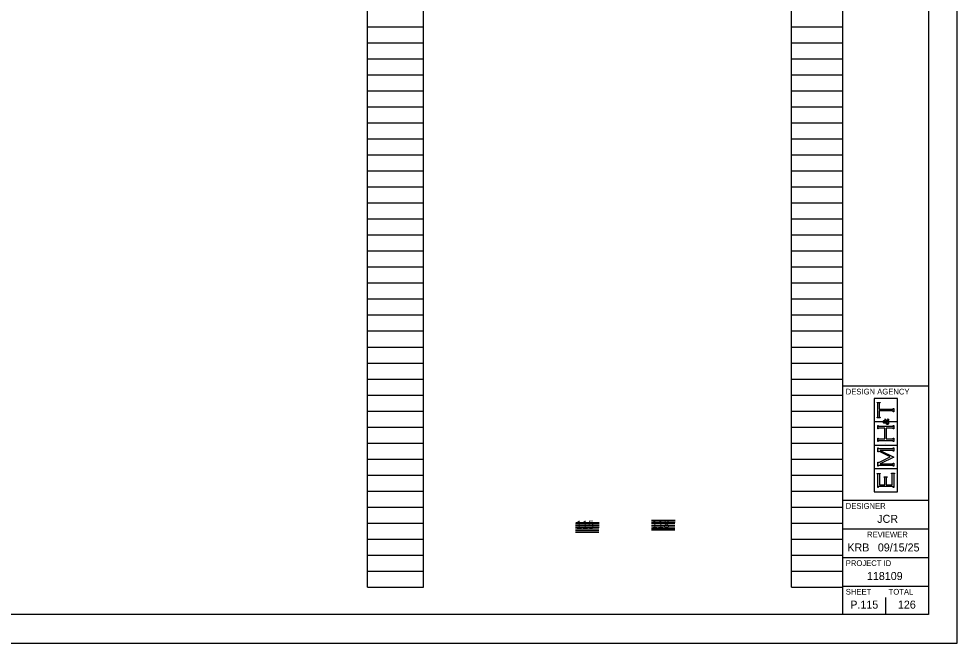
# Model space of a CAD drawing. Extents: x 0 to 34, y 0 to 22.
# Drawn here: x 17.58 to 34, y 0 to 10.92 of the extents above; entities that cross this region are included whole.
import ezdxf

# ---------------------------------------------------------------- set-up
doc = ezdxf.new("R2010")
doc.units = 0
for name, color, linetype in [('SH_Border', 7, 'Continuous'), ('SH_Cut_Line', 7, 'Continuous'), ('SH_Data', 7, 'Continuous'), ('SH_Text', 7, 'Continuous')]:
    doc.layers.add(name, color=color, linetype=linetype)

msp = doc.modelspace()

# ---------------------------------------------------------------- linework, layer by layer
at = {"layer": 'SH_Border'}
for p, q in [((32, 0.5), (32, 21.5)), ((32, 4.5), (33.5, 4.5)), ((32, 2.5), (33.5, 2.5)), ((32, 2), (33.5, 2)), ((32, 1.5), (33.5, 1.5)), ((32, 1), (33.5, 1))]:
    msp.add_line(p, q, dxfattribs=at)
msp.add_lwpolyline([(1.5, 21.5), (33.5, 21.5), (33.5, 0.5), (1.5, 0.5)], close=True, dxfattribs=at)
at = {"layer": 'SH_Cut_Line'}
msp.add_lwpolyline([(0, 0), (34, 0), (34, 22), (0, 22)], close=True, dxfattribs=at)
at = {"layer": 'SH_Data'}
for p, q in [((23.68, 0.98), (23.68, 21.14)), ((24.66, 0.98), (24.66, 21.14)), ((31.1, 0.98), (31.1, 21.14)), ((32, 0.98), (32, 21.14)), ((23.68, 10.78), (24.66, 10.78)), ((31.1, 10.78), (32, 10.78)), ((23.68, 10.5), (24.66, 10.5)), ((31.1, 10.5), (32, 10.5)), ((23.68, 10.22), (24.66, 10.22)), ((31.1, 10.22), (32, 10.22)), ((23.68, 9.94), (24.66, 9.94)), ((31.1, 9.94), (32, 9.94)), ((23.68, 9.66), (24.66, 9.66)), ((31.1, 9.66), (32, 9.66)), ((23.68, 9.38), (24.66, 9.38)), ((31.1, 9.38), (32, 9.38)), ((23.68, 9.1), (24.66, 9.1)), ((31.1, 9.1), (32, 9.1)), ((23.68, 8.82), (24.66, 8.82)), ((31.1, 8.82), (32, 8.82)), ((23.68, 8.54), (24.66, 8.54)), ((31.1, 8.54), (32, 8.54)), ((23.68, 8.26), (24.66, 8.26)), ((31.1, 8.26), (32, 8.26)), ((23.68, 7.98), (24.66, 7.98)), ((31.1, 7.98), (32, 7.98)), ((23.68, 7.7), (24.66, 7.7)), ((31.1, 7.7), (32, 7.7)), ((23.68, 7.42), (24.66, 7.42)), ((31.1, 7.42), (32, 7.42)), ((23.68, 7.14), (24.66, 7.14)), ((31.1, 7.14), (32, 7.14)), ((23.68, 6.86), (24.66, 6.86)), ((31.1, 6.86), (32, 6.86)), ((23.68, 6.58), (24.66, 6.58)), ((31.1, 6.58), (32, 6.58)), ((23.68, 6.3), (24.66, 6.3)), ((31.1, 6.3), (32, 6.3)), ((23.68, 6.02), (24.66, 6.02)), ((31.1, 6.02), (32, 6.02)), ((23.68, 5.74), (24.66, 5.74)), ((31.1, 5.74), (32, 5.74)), ((23.68, 5.46), (24.66, 5.46)), ((31.1, 5.46), (32, 5.46)), ((23.68, 5.18), (24.66, 5.18)), ((31.1, 5.18), (32, 5.18)), ((23.68, 4.9), (24.66, 4.9)), ((31.1, 4.9), (32, 4.9)), ((23.68, 4.62), (24.66, 4.62)), ((31.1, 4.62), (32, 4.62)), ((23.68, 4.34), (24.66, 4.34)), ((31.1, 4.34), (32, 4.34)), ((32.952, 4.279), (32.547, 4.279)), ((32.547, 4.279), (32.547, 3.875)), ((32.952, 3.875), (32.952, 4.279)), ((32.598, 4.204), (32.598, 4.211)), ((32.598, 4.211), (32.65, 4.211)), ((32.603, 4.203), (32.598, 4.204)), ((32.606, 4.201), (32.603, 4.203)), ((32.608, 4.199), (32.606, 4.201)), ((32.61, 4.196), (32.608, 4.199)), ((32.611, 4.192), (32.61, 4.196)), ((32.611, 4.187), (32.611, 4.192)), ((32.611, 3.968), (32.611, 4.187)), ((32.638, 4.196), (32.637, 4.192)), ((32.637, 4.192), (32.637, 4.187)), ((32.637, 4.187), (32.637, 4.093)), ((32.64, 4.199), (32.638, 4.196)), ((32.642, 4.201), (32.64, 4.199)), ((32.645, 4.203), (32.642, 4.201)), ((32.65, 4.204), (32.645, 4.203)), ((32.65, 4.211), (32.65, 4.204)), ((32.88, 4.101), (32.881, 4.106)), ((32.881, 4.106), (32.888, 4.106)), ((32.888, 4.106), (32.888, 4.048)), ((23.68, 4.06), (24.66, 4.06)), ((31.1, 4.06), (32, 4.06)), ((32.598, 3.95), (32.603, 3.951)), ((32.598, 3.944), (32.598, 3.95)), ((32.65, 3.944), (32.598, 3.944)), ((32.603, 3.951), (32.606, 3.953)), ((32.606, 3.953), (32.608, 3.955)), ((32.608, 3.955), (32.61, 3.958)), ((32.61, 3.958), (32.611, 3.962)), ((32.611, 3.962), (32.611, 3.968)), ((32.637, 4.093), (32.864, 4.093)), ((32.864, 4.061), (32.637, 4.061)), ((32.637, 4.061), (32.637, 3.968)), ((32.637, 3.968), (32.637, 3.962)), ((32.637, 3.962), (32.638, 3.958)), ((32.638, 3.958), (32.64, 3.955)), ((32.64, 3.955), (32.642, 3.953)), ((32.642, 3.953), (32.645, 3.951)), ((32.645, 3.951), (32.65, 3.95)), ((32.65, 3.95), (32.65, 3.944)), ((32.864, 4.093), (32.869, 4.093)), ((32.87, 4.061), (32.864, 4.061)), ((32.869, 4.093), (32.873, 4.094)), ((32.874, 4.06), (32.87, 4.061)), ((32.873, 4.094), (32.876, 4.096)), ((32.876, 4.059), (32.874, 4.06)), ((32.876, 4.096), (32.878, 4.097)), ((32.878, 4.057), (32.876, 4.059)), ((32.878, 4.097), (32.88, 4.101)), ((32.88, 4.053), (32.878, 4.057)), ((32.881, 4.048), (32.88, 4.053)), ((32.888, 4.048), (32.881, 4.048)), ((23.68, 3.78), (24.66, 3.78)), ((31.1, 3.78), (32, 3.78)), ((32.547, 3.875), (32.696, 3.875)), ((32.696, 3.869), (32.547, 3.869)), ((32.547, 3.869), (32.547, 3.465)), ((32.611, 3.749), (32.611, 3.807)), ((32.611, 3.807), (32.617, 3.807)), ((32.617, 3.807), (32.619, 3.802)), ((32.619, 3.802), (32.62, 3.798)), ((32.62, 3.798), (32.623, 3.797)), ((32.623, 3.797), (32.625, 3.795)), ((32.625, 3.795), (32.629, 3.794)), ((32.629, 3.794), (32.635, 3.794)), ((32.635, 3.794), (32.864, 3.794)), ((32.696, 3.875), (32.696, 3.869)), ((32.703, 3.879), (32.705, 3.883)), ((32.703, 3.873), (32.703, 3.879)), ((32.703, 3.868), (32.703, 3.873)), ((32.705, 3.863), (32.703, 3.868)), ((32.705, 3.883), (32.708, 3.887)), ((32.708, 3.858), (32.705, 3.863)), ((32.708, 3.887), (32.711, 3.89)), ((32.709, 3.879), (32.708, 3.876)), ((32.708, 3.876), (32.708, 3.873)), ((32.708, 3.873), (32.708, 3.869)), ((32.708, 3.869), (32.71, 3.866)), ((32.712, 3.853), (32.708, 3.858)), ((32.712, 3.881), (32.709, 3.879)), ((32.71, 3.866), (32.712, 3.864)), ((32.711, 3.89), (32.715, 3.892)), ((32.714, 3.883), (32.712, 3.881)), ((32.712, 3.864), (32.715, 3.862)), ((32.718, 3.85), (32.712, 3.853)), ((32.716, 3.884), (32.714, 3.883)), ((32.715, 3.892), (32.72, 3.892)), ((32.715, 3.862), (32.718, 3.861)), ((32.72, 3.884), (32.716, 3.884)), ((32.718, 3.861), (32.721, 3.861)), ((32.726, 3.85), (32.718, 3.85)), ((32.72, 3.892), (32.725, 3.892)), ((32.724, 3.884), (32.72, 3.884)), ((32.721, 3.861), (32.723, 3.861)), ((32.723, 3.861), (32.725, 3.862)), ((32.728, 3.882), (32.724, 3.884)), ((32.725, 3.892), (32.729, 3.89)), ((32.725, 3.862), (32.728, 3.862)), ((32.729, 3.85), (32.726, 3.85)), ((32.731, 3.88), (32.728, 3.882)), ((32.728, 3.862), (32.731, 3.863)), ((32.729, 3.89), (32.732, 3.887)), ((32.731, 3.85), (32.729, 3.85)), ((32.734, 3.877), (32.731, 3.88)), ((32.731, 3.863), (32.735, 3.865)), ((32.734, 3.851), (32.731, 3.85)), ((32.732, 3.887), (32.736, 3.883)), ((32.737, 3.872), (32.734, 3.877)), ((32.737, 3.852), (32.734, 3.851)), ((32.735, 3.865), (32.74, 3.867)), ((32.736, 3.883), (32.74, 3.878)), ((32.74, 3.867), (32.737, 3.872)), ((32.741, 3.853), (32.737, 3.852)), ((32.738, 3.893), (32.738, 3.922)), ((32.738, 3.922), (32.741, 3.922)), ((32.741, 3.893), (32.738, 3.893)), ((32.74, 3.878), (32.744, 3.869)), ((32.741, 3.922), (32.741, 3.918)), ((32.741, 3.918), (32.742, 3.915)), ((32.742, 3.896), (32.741, 3.895)), ((32.741, 3.895), (32.741, 3.893)), ((32.746, 3.855), (32.741, 3.853)), ((32.742, 3.915), (32.743, 3.913)), ((32.743, 3.897), (32.742, 3.896)), ((32.743, 3.913), (32.745, 3.911)), ((32.745, 3.899), (32.743, 3.897)), ((32.744, 3.869), (32.754, 3.875)), ((32.745, 3.911), (32.749, 3.908)), ((32.746, 3.899), (32.745, 3.899)), ((32.748, 3.899), (32.746, 3.899)), ((32.752, 3.844), (32.746, 3.855)), ((32.755, 3.899), (32.748, 3.899)), ((32.749, 3.908), (32.756, 3.904)), ((32.756, 3.86), (32.751, 3.857)), ((32.751, 3.857), (32.754, 3.852)), ((32.757, 3.837), (32.752, 3.844)), ((32.754, 3.875), (32.764, 3.881)), ((32.754, 3.852), (32.757, 3.848)), ((32.763, 3.895), (32.755, 3.899)), ((32.756, 3.904), (32.763, 3.9)), ((32.761, 3.863), (32.756, 3.86)), ((32.757, 3.848), (32.761, 3.845)), ((32.763, 3.833), (32.757, 3.837)), ((32.764, 3.865), (32.761, 3.863)), ((32.761, 3.845), (32.765, 3.843)), ((32.763, 3.9), (32.77, 3.896)), ((32.772, 3.887), (32.763, 3.895)), ((32.768, 3.829), (32.763, 3.833)), ((32.764, 3.881), (32.772, 3.887)), ((32.768, 3.867), (32.764, 3.865)), ((32.765, 3.843), (32.769, 3.841)), ((32.774, 3.872), (32.768, 3.867)), ((32.774, 3.827), (32.768, 3.829)), ((32.769, 3.841), (32.773, 3.841)), ((32.77, 3.896), (32.776, 3.891)), ((32.773, 3.841), (32.778, 3.841)), ((32.782, 3.878), (32.774, 3.872)), ((32.779, 3.827), (32.774, 3.827)), ((32.776, 3.891), (32.781, 3.895)), ((32.778, 3.841), (32.782, 3.843)), ((32.779, 3.923), (32.781, 3.926)), ((32.782, 3.922), (32.779, 3.923)), ((32.785, 3.827), (32.779, 3.827)), ((32.781, 3.926), (32.787, 3.924)), ((32.781, 3.895), (32.784, 3.898)), ((32.785, 3.921), (32.782, 3.922)), ((32.786, 3.873), (32.782, 3.878)), ((32.782, 3.843), (32.786, 3.846)), ((32.784, 3.898), (32.786, 3.901)), ((32.786, 3.919), (32.785, 3.921)), ((32.79, 3.829), (32.785, 3.827)), ((32.788, 3.917), (32.786, 3.919)), ((32.786, 3.901), (32.788, 3.904)), ((32.791, 3.886), (32.786, 3.881)), ((32.786, 3.881), (32.791, 3.876)), ((32.788, 3.869), (32.786, 3.873)), ((32.786, 3.846), (32.789, 3.849)), ((32.787, 3.924), (32.792, 3.921)), ((32.789, 3.914), (32.788, 3.917)), ((32.788, 3.904), (32.789, 3.908)), ((32.79, 3.867), (32.788, 3.869)), ((32.789, 3.911), (32.789, 3.914)), ((32.789, 3.908), (32.789, 3.911)), ((32.789, 3.849), (32.791, 3.853)), ((32.791, 3.864), (32.79, 3.867)), ((32.793, 3.834), (32.79, 3.829)), ((32.794, 3.89), (32.791, 3.886)), ((32.791, 3.876), (32.795, 3.87)), ((32.791, 3.861), (32.791, 3.864)), ((32.791, 3.859), (32.791, 3.861)), ((32.791, 3.853), (32.791, 3.859)), ((32.792, 3.921), (32.795, 3.918)), ((32.797, 3.838), (32.793, 3.834)), ((32.796, 3.894), (32.794, 3.89)), ((32.795, 3.918), (32.798, 3.914)), ((32.795, 3.87), (32.797, 3.866)), ((32.798, 3.897), (32.796, 3.894)), ((32.797, 3.866), (32.798, 3.861)), ((32.799, 3.844), (32.797, 3.838)), ((32.798, 3.914), (32.799, 3.91)), ((32.799, 3.901), (32.798, 3.897)), ((32.798, 3.861), (32.799, 3.857)), ((32.799, 3.91), (32.799, 3.905)), ((32.799, 3.905), (32.799, 3.901)), ((32.803, 3.869), (32.799, 3.875)), ((32.799, 3.875), (32.952, 3.875)), ((32.799, 3.857), (32.799, 3.852)), ((32.799, 3.852), (32.799, 3.844)), ((32.952, 3.869), (32.803, 3.869)), ((32.864, 3.794), (32.869, 3.794)), ((32.869, 3.794), (32.873, 3.795)), ((32.873, 3.795), (32.876, 3.797)), ((32.876, 3.797), (32.878, 3.798)), ((32.878, 3.798), (32.88, 3.802)), ((32.88, 3.802), (32.881, 3.807)), ((32.881, 3.807), (32.888, 3.807)), ((32.888, 3.807), (32.888, 3.749)), ((32.952, 3.465), (32.952, 3.869)), ((32.617, 3.749), (32.611, 3.749)), ((32.618, 3.754), (32.617, 3.749)), ((32.62, 3.758), (32.618, 3.754)), ((32.623, 3.76), (32.62, 3.758)), ((32.625, 3.761), (32.623, 3.76)), ((32.629, 3.762), (32.625, 3.761)), ((32.635, 3.762), (32.629, 3.762)), ((32.732, 3.762), (32.635, 3.762)), ((32.732, 3.572), (32.732, 3.762)), ((32.864, 3.762), (32.759, 3.762)), ((32.759, 3.762), (32.759, 3.572)), ((32.87, 3.762), (32.864, 3.762)), ((32.874, 3.761), (32.87, 3.762)), ((32.876, 3.76), (32.874, 3.761)), ((32.878, 3.758), (32.876, 3.76)), ((32.88, 3.754), (32.878, 3.758)), ((32.881, 3.749), (32.88, 3.754)), ((32.888, 3.749), (32.881, 3.749)), ((23.68, 3.5), (24.66, 3.5)), ((31.1, 3.5), (32, 3.5)), ((32.547, 3.465), (32.952, 3.465)), ((32.952, 3.459), (32.547, 3.459)), ((32.547, 3.459), (32.547, 3.055)), ((32.611, 3.527), (32.611, 3.585)), ((32.611, 3.585), (32.617, 3.585)), ((32.617, 3.527), (32.611, 3.527)), ((32.617, 3.585), (32.619, 3.58)), ((32.618, 3.532), (32.617, 3.527)), ((32.62, 3.536), (32.618, 3.532)), ((32.619, 3.58), (32.62, 3.576)), ((32.62, 3.576), (32.623, 3.574)), ((32.623, 3.537), (32.62, 3.536)), ((32.623, 3.574), (32.625, 3.573)), ((32.625, 3.539), (32.623, 3.537)), ((32.625, 3.573), (32.629, 3.572)), ((32.629, 3.54), (32.625, 3.539)), ((32.629, 3.572), (32.635, 3.572)), ((32.635, 3.54), (32.629, 3.54)), ((32.635, 3.572), (32.732, 3.572)), ((32.864, 3.54), (32.635, 3.54)), ((32.75, 3.5), (32.75, 3.5)), ((32.759, 3.572), (32.864, 3.572)), ((32.864, 3.572), (32.87, 3.572)), ((32.87, 3.54), (32.864, 3.54)), ((32.87, 3.572), (32.874, 3.573)), ((32.874, 3.539), (32.87, 3.54)), ((32.874, 3.573), (32.876, 3.574)), ((32.876, 3.538), (32.874, 3.539)), ((32.876, 3.574), (32.878, 3.576)), ((32.878, 3.536), (32.876, 3.538)), ((32.878, 3.576), (32.88, 3.58)), ((32.88, 3.532), (32.878, 3.536)), ((32.88, 3.58), (32.881, 3.585)), ((32.881, 3.527), (32.88, 3.532)), ((32.881, 3.585), (32.888, 3.585)), ((32.888, 3.527), (32.881, 3.527)), ((32.888, 3.585), (32.888, 3.527)), ((32.952, 3.055), (32.952, 3.459)), ((32.611, 3.345), (32.611, 3.418)), ((32.611, 3.418), (32.617, 3.418)), ((32.617, 3.345), (32.611, 3.345)), ((32.617, 3.418), (32.619, 3.412)), ((32.62, 3.352), (32.617, 3.345)), ((32.619, 3.412), (32.62, 3.409)), ((32.62, 3.409), (32.623, 3.407)), ((32.622, 3.355), (32.62, 3.352)), ((32.626, 3.355), (32.622, 3.355)), ((32.623, 3.407), (32.625, 3.405)), ((32.625, 3.405), (32.629, 3.405)), ((32.629, 3.355), (32.626, 3.355)), ((32.629, 3.405), (32.635, 3.405)), ((32.633, 3.353), (32.629, 3.355)), ((32.64, 3.35), (32.633, 3.353)), ((32.635, 3.405), (32.864, 3.405)), ((32.825, 3.257), (32.64, 3.35)), ((32.864, 3.373), (32.654, 3.373)), ((32.654, 3.373), (32.888, 3.255)), ((32.864, 3.405), (32.869, 3.405)), ((32.87, 3.373), (32.864, 3.373)), ((32.869, 3.405), (32.873, 3.405)), ((32.874, 3.372), (32.87, 3.373)), ((32.873, 3.405), (32.876, 3.407)), ((32.876, 3.37), (32.874, 3.372)), ((32.876, 3.407), (32.878, 3.409)), ((32.878, 3.369), (32.876, 3.37)), ((32.878, 3.409), (32.88, 3.412)), ((32.88, 3.365), (32.878, 3.369)), ((32.88, 3.412), (32.881, 3.418)), ((32.881, 3.36), (32.88, 3.365)), ((32.881, 3.418), (32.888, 3.418)), ((32.888, 3.36), (32.881, 3.36)), ((32.888, 3.418), (32.888, 3.36)), ((23.68, 3.22), (24.66, 3.22)), ((31.1, 3.22), (32, 3.22)), ((32.611, 3.096), (32.611, 3.168)), ((32.611, 3.168), (32.617, 3.168)), ((32.617, 3.168), (32.62, 3.162)), ((32.62, 3.162), (32.622, 3.158)), ((32.622, 3.158), (32.626, 3.158)), ((32.626, 3.158), (32.627, 3.158)), ((32.627, 3.158), (32.633, 3.161)), ((32.633, 3.161), (32.641, 3.165)), ((32.641, 3.165), (32.825, 3.257)), ((32.888, 3.255), (32.654, 3.138)), ((32.654, 3.138), (32.864, 3.138)), ((32.864, 3.138), (32.869, 3.138)), ((32.869, 3.138), (32.873, 3.139)), ((32.873, 3.139), (32.876, 3.141)), ((32.876, 3.141), (32.878, 3.143)), ((32.878, 3.143), (32.88, 3.146)), ((32.88, 3.146), (32.881, 3.151)), ((32.881, 3.151), (32.888, 3.151)), ((32.888, 3.151), (32.888, 3.096)), ((32.547, 3.055), (32.952, 3.055)), ((32.952, 3.049), (32.547, 3.049)), ((32.547, 3.049), (32.547, 2.645)), ((32.598, 2.962), (32.598, 2.969)), ((32.598, 2.969), (32.65, 2.969)), ((32.603, 2.961), (32.598, 2.962)), ((32.606, 2.959), (32.603, 2.961)), ((32.608, 2.957), (32.606, 2.959)), ((32.61, 2.955), (32.608, 2.957)), ((32.617, 3.096), (32.611, 3.096)), ((32.618, 3.102), (32.617, 3.096)), ((32.62, 3.105), (32.618, 3.102)), ((32.623, 3.107), (32.62, 3.105)), ((32.625, 3.109), (32.623, 3.107)), ((32.629, 3.109), (32.625, 3.109)), ((32.635, 3.109), (32.629, 3.109)), ((32.864, 3.109), (32.635, 3.109)), ((32.64, 2.957), (32.638, 2.955)), ((32.642, 2.959), (32.64, 2.957)), ((32.645, 2.961), (32.642, 2.959)), ((32.65, 2.962), (32.645, 2.961)), ((32.65, 2.969), (32.65, 2.962)), ((32.848, 2.965), (32.848, 2.972)), ((32.848, 2.972), (32.901, 2.972)), ((32.853, 2.964), (32.848, 2.965)), ((32.857, 2.962), (32.853, 2.964)), ((32.859, 2.96), (32.857, 2.962)), ((32.86, 2.958), (32.859, 2.96)), ((32.861, 2.953), (32.86, 2.958)), ((32.87, 3.109), (32.864, 3.109)), ((32.874, 3.109), (32.87, 3.109)), ((32.876, 3.107), (32.874, 3.109)), ((32.878, 3.105), (32.876, 3.107)), ((32.88, 3.102), (32.878, 3.105)), ((32.881, 3.096), (32.88, 3.102)), ((32.888, 3.096), (32.881, 3.096)), ((32.889, 2.957), (32.888, 2.953)), ((32.891, 2.96), (32.889, 2.957)), ((32.892, 2.962), (32.891, 2.96)), ((32.896, 2.964), (32.892, 2.962)), ((32.901, 2.965), (32.896, 2.964)), ((32.901, 2.972), (32.901, 2.965)), ((32.952, 2.645), (32.952, 3.049)), ((23.68, 2.94), (24.66, 2.94)), ((31.1, 2.94), (32, 2.94)), ((32.611, 2.951), (32.61, 2.955)), ((32.611, 2.945), (32.611, 2.951)), ((32.611, 2.725), (32.611, 2.945)), ((32.638, 2.955), (32.638, 2.951)), ((32.638, 2.951), (32.638, 2.945)), ((32.638, 2.945), (32.638, 2.77)), ((32.719, 2.902), (32.719, 2.908)), ((32.719, 2.908), (32.772, 2.908)), ((32.724, 2.901), (32.719, 2.902)), ((32.728, 2.899), (32.724, 2.901)), ((32.729, 2.896), (32.728, 2.899)), ((32.731, 2.894), (32.729, 2.896)), ((32.732, 2.89), (32.731, 2.894)), ((32.732, 2.884), (32.732, 2.89)), ((32.732, 2.77), (32.732, 2.884)), ((32.76, 2.894), (32.759, 2.89)), ((32.759, 2.89), (32.759, 2.884)), ((32.759, 2.884), (32.759, 2.77)), ((32.761, 2.896), (32.76, 2.894)), ((32.763, 2.899), (32.761, 2.896)), ((32.767, 2.901), (32.763, 2.899)), ((32.772, 2.902), (32.767, 2.901)), ((32.772, 2.908), (32.772, 2.902)), ((32.861, 2.948), (32.861, 2.953)), ((32.861, 2.77), (32.861, 2.948)), ((32.888, 2.953), (32.888, 2.948)), ((32.888, 2.948), (32.888, 2.725)), ((23.68, 2.66), (24.66, 2.66)), ((31.1, 2.66), (32, 2.66)), ((32.547, 2.645), (32.952, 2.645)), ((32.617, 2.725), (32.611, 2.725)), ((32.619, 2.73), (32.617, 2.725)), ((32.62, 2.734), (32.619, 2.73)), ((32.623, 2.735), (32.62, 2.734)), ((32.625, 2.737), (32.623, 2.735)), ((32.629, 2.738), (32.625, 2.737)), ((32.635, 2.738), (32.629, 2.738)), ((32.864, 2.738), (32.635, 2.738)), ((32.638, 2.77), (32.732, 2.77)), ((32.759, 2.77), (32.861, 2.77)), ((32.87, 2.738), (32.864, 2.738)), ((32.874, 2.737), (32.87, 2.738)), ((32.876, 2.735), (32.874, 2.737)), ((32.878, 2.734), (32.876, 2.735)), ((32.88, 2.73), (32.878, 2.734)), ((32.881, 2.725), (32.88, 2.73)), ((32.888, 2.725), (32.881, 2.725)), ((23.68, 2.38), (24.66, 2.38)), ((31.1, 2.38), (32, 2.38)), ((23.68, 2.1), (24.66, 2.1)), ((31.1, 2.1), (32, 2.1)), ((23.68, 1.82), (24.66, 1.82)), ((31.1, 1.82), (32, 1.82)), ((23.68, 1.54), (24.66, 1.54)), ((31.1, 1.54), (32, 1.54)), ((23.68, 1.26), (24.66, 1.26)), ((31.1, 1.26), (32, 1.26)), ((23.68, 0.98), (24.66, 0.98)), ((31.1, 0.98), (32, 0.98)), ((32.375, 0.675), (32.375, 0.675)), ((32.75, 0.5), (32.75, 0.8))]:
    msp.add_line(p, q, dxfattribs=at)
at = {"layer": 'SH_Text'}
for p, q in [((28.652, 2.152), (29.064, 2.152)), ((27.32, 1.998), (27.732, 1.998)), ((27.321, 2.06), (27.733, 2.06)), ((27.321, 2.027), (27.733, 2.027)), ((27.323, 2.086), (27.735, 2.086)), ((27.324, 2.114), (27.736, 2.114)), ((28.648, 2.036), (29.06, 2.036)), ((28.648, 2.007), (29.06, 2.007)), ((28.648, 1.981), (29.059, 1.981)), ((28.649, 2.098), (29.061, 2.098)), ((28.649, 2.065), (29.061, 2.065)), ((28.651, 2.124), (29.063, 2.124)), ((27.319, 1.943), (27.731, 1.943)), ((27.32, 1.969), (27.732, 1.969))]:
    msp.add_line(p, q, dxfattribs=at)

# ---------------------------------------------------------------- texts
at = {"layer": 'SH_Data'}
for s, height, p in [('DESIGN AGENCY', 0.1, (32.05, 4.35)), ('DESIGNER', 0.1, (32.05, 2.35)), ('JCR', 0.14, (32.6, 2.105)), ('REVIEWER', 0.1, (32.422, 1.85)), ('KRB', 0.14, (32.078, 1.605)), ('09/15/25', 0.14, (32.611, 1.605)), ('PROJECT ID', 0.1, (32.05, 1.35)), ('118109', 0.14, (32.42, 1.105)), ('SHEET', 0.1, (32.05, 0.85)), ('TOTAL', 0.1, (32.8, 0.85)), ('P.115', 0.14, (32.129, 0.605)), ('126', 0.14, (32.962, 0.605))]:
    msp.add_text(s, height=height, dxfattribs=at).set_placement(p)
at = {"layer": 'SH_Text'}
for s, p in [('115', (27.332, 2.004)), ('118', (28.654, 2.01))]:
    msp.add_text(s, height=0.14, dxfattribs=at).set_placement(p)

doc.saveas('drawing.dxf')
